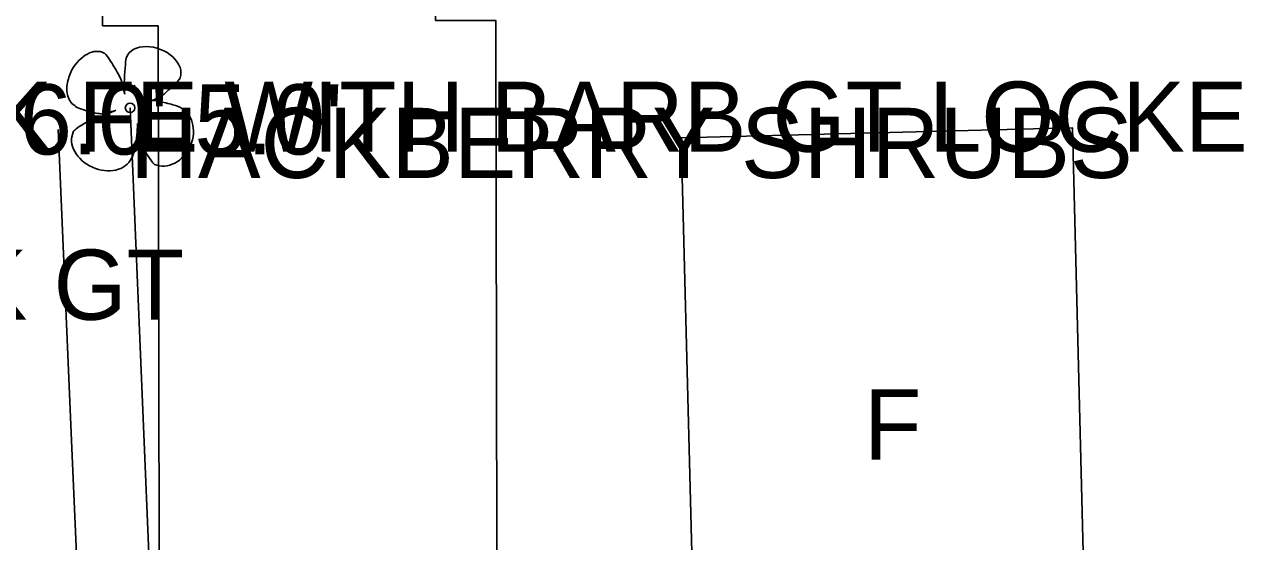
# Model space of a CAD drawing. Extents: x 1304270 to 1306561, y 1876019 to 1876752.
# Drawn here: x 1305034.9 to 1305121.6, y 1876470.3 to 1876507.2 of the extents above; entities that cross this region are included whole.
import ezdxf

# ---------------------------------------------------------------- set-up
doc = ezdxf.new("R2010")
doc.units = 0
for name, color, linetype in [('S_BUILDING', 7, 'Continuous'), ('S_BUILDING_ANNOT', 7, 'Continuous'), ('S_DRIVEWAY', 7, 'Continuous'), ('S_FENCE', 7, 'Continuous'), ('S_GATE_ANNOT', 7, 'Continuous'), ('S_MSC_PT_SYM', 7, 'Continuous'), ('S_SURVEY_TEXT_ANNOT', 7, 'Continuous'), ('S_TREE', 7, 'Continuous'), ('S_TREE_ANNOT', 7, 'Continuous')]:
    doc.layers.add(name, color=color, linetype=linetype)

msp = doc.modelspace()

# ---------------------------------------------------------------- linework, layer by layer
at = {"layer": 'S_BUILDING'}
for points in [[(1305044.478, 1876457.268), (1305044.379, 1876507.056), (1305040.426, 1876507.048), (1305040.408, 1876515.917), (1305043.37, 1876515.923), (1305043.269, 1876566.204), (1305064.005, 1876566.245), (1305064.122, 1876507.428), (1305068.402, 1876507.437), (1305068.502, 1876457.316)], [(1305110.49, 1876458.23), (1305109.436, 1876499.786), (1305081.6, 1876499.079), (1305082.654, 1876457.523)]]:
    msp.add_lwpolyline(points, close=True, dxfattribs=at)
at = {"layer": 'S_DRIVEWAY'}
msp.add_lwpolyline([(1305045.177, 1876426.293), (1305040.867, 1876432.816), (1305039.241, 1876454.279), (1305038.253, 1876476.972), (1305037.265, 1876499.664)], dxfattribs=at)
at = {"layer": 'S_FENCE'}
msp.add_line((1305040.571, 1876502.979), (1305042.703, 1876502.753), dxfattribs=at)
msp.add_lwpolyline([(1305040.571, 1876502.979), (1305042.703, 1876502.753)], dxfattribs=at)
msp.add_lwpolyline([(1305040.571, 1876502.979), (1305042.703, 1876502.753)], dxfattribs=at)
at = {"layer": 'S_MSC_PT_SYM'}
for points in [[(1305040.571, 1876502.979), (1305040.571, 1876503.029), (1305040.571, 1876502.979), (1305040.521, 1876502.979), (1305040.571, 1876502.979), (1305040.571, 1876502.929), (1305040.571, 1876502.979), (1305040.621, 1876502.979)], [(1305042.703, 1876502.753), (1305042.703, 1876502.803), (1305042.703, 1876502.753), (1305042.653, 1876502.753), (1305042.703, 1876502.753), (1305042.703, 1876502.703), (1305042.703, 1876502.753), (1305042.753, 1876502.753)]]:
    msp.add_lwpolyline(points, dxfattribs=at)
at = {"layer": 'S_TREE'}
for p, q in [((1305042.019, 1876502.187), (1305041.776, 1876503.08)), ((1305043.967, 1876501.727), (1305044.346, 1876501.89)), ((1305041.37, 1876501.024), (1305040.396, 1876500.807)), ((1305042.387, 1876501.208), (1305043.913, 1876464.698)), ((1305042.905, 1876500.093), (1305042.983, 1876499.654))]:
    msp.add_line(p, q, dxfattribs=at)
msp.add_circle((1305042.387, 1876501.208), 0.341, dxfattribs=at)
for centre, major_axis, ratio, start_param, end_param in [((1305039.5, 1876503.225), (-1.031, -1.884), 0.662338, 3.141593, 6.283185), ((1305044.048, 1876504.095), (1.894, -0.744), 0.673998, 0, 3.141593), ((1305041.154, 1876504.095), (0.622, -1.015), 0.083512, 0, 3.141593), ((1305042.087, 1876503.513), (-0.068, -1.326), 0.068203, 3.141593, 6.283185), ((1305045.144, 1876502.62), (-0.798, -0.73), 0.092159, 0, 3.141593), ((1305039.432, 1876501.074), (0.964, -0.267), 0.113563, 3.141593, 6.283185), ((1305040.332, 1876500.581), (1.038, 0.443), 0.002756, 3.141593, 6.283185), ((1305044.928, 1876501.497), (0.96, -0.23), 0.056001, 0, 3.141593), ((1305045.006, 1876499.221), (0.883, 2.046), 0.81717, 3.141593, 6.283185), ((1305038.817, 1876499.81), (0.477, 0.328), 0.136309, 0, 3.141593), ((1305042.669, 1876498.927), (0.189, 1.312), 0.114148, 3.141593, 5.822668), ((1305040.41, 1876498.548), (2.07, -0.933), 0.760068, 3.141593, 6.283185), ((1305043.237, 1876498.883), (0.254, -0.771), 0.051603, 3.141593, 6.283185), ((1305043.812, 1876497.645), (-0.321, 0.467), 0.094289, 0, 3.141593)]:
    msp.add_ellipse(centre, major_axis=major_axis, ratio=ratio, start_param=start_param, end_param=end_param, dxfattribs=at)

# ---------------------------------------------------------------- texts
at = {"layer": 'S_BUILDING_ANNOT'}
msp.add_text('F', height=5, dxfattribs=at).set_placement((1305094.608, 1876476.154))
at = {"layer": 'S_GATE_ANNOT'}
for s, p in [("6.0' 5.0'", (1305034.535, 1876497.883)), ("4' 2.5' MTL CHAINLINK GT", (1304964.907, 1876486.11))]:
    msp.add_text(s, height=5, dxfattribs=at).set_placement(p)
at = {"layer": 'S_SURVEY_TEXT_ANNOT'}
msp.add_text('CHAINLINK FE WITH BARB GT LOCKE', height=5, dxfattribs=at).set_placement((1305001.167, 1876498.074))
at = {"layer": 'S_TREE_ANNOT'}
msp.add_text('HACKBERRY SHRUBS', height=5, dxfattribs=at).set_placement((1305042.387, 1876496.208))

doc.saveas('drawing.dxf')
